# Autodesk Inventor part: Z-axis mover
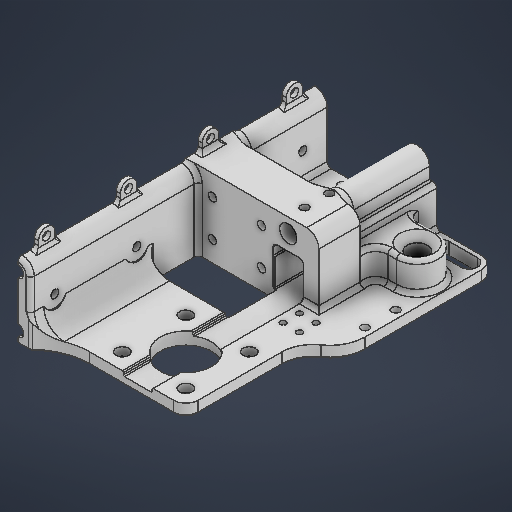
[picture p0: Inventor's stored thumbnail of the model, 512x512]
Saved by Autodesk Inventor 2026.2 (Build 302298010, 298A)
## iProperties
Created: 2026-04
Part Number: Z-axis mover
Material: 일반
Document SubType Name: Modeling
Designer: work
Density: 1 g/cm^3
Appearance: 기본값
Author: work
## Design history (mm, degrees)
sketch "스케치1"
  geometry: L1 (0, 0)-(8, 0); L2 (0, 0)-(0, 8); L3 (0, 0)-(-8, 0); L4 (0, 0)-(0, -8); L5 (0, 0)-(50, 0); L6 (0, 0)-(-50, 0); L7 (0, 0)-(0, 50); L8 (25, 0)-(25, -380); L9 (-25, 0)-(-25, -380); L10 (-25, 0)-(-25, 70); L11 (25, -380)-(-25, -380); L12 (25, 0)-(25, 0); L13 (25, 0)-(25, 120); L14 (-37.5, -395)-(37.5, -395); L15 (37.5, -395)-(37.5, -365); L16 (37.5, -365)-(-37.5, -365); L17 (-37.5, -365)-(-37.5, -395); L18 (-37.5, -395)-(37.5, -365); L19 (37.5, -395)-(-37.5, -365); L20 (-62.5, 38)-(62.5, 38); L21 (62.5, 38)-(62.5, -38); L22 (62.5, -38)-(-62.5, -38); L23 (-62.5, -38)-(-62.5, 38); L24 (-62.5, 38)-(62.5, -38); L25 (62.5, 38)-(-62.5, -38); L26 (62.5, -25)-(-62.5, -25); L27 (17, 38)-(-17, 38); L28 (-17, 38)-(-17, 61); L29 (-17, 61)-(17, 61); L30 (17, 61)-(17, 38); L31 (-22, 60.236)-(-22, 100); L32 (-22, 100)-(-28, 100); L33 (-28, 100)-(-28, -380); L34 (-28, -380)-(-22, -380); L35 (-22, -380)-(-22, 100); L36 (-40, 38)-(40, 38); L37 (40, 38)-(40, 18); L38 (40, 18)-(-40, 18); L39 (-40, 18)-(-40, 38); C1 r 5.25 at (0, 0); C2 r 11.3 at (0, 0); C3 r 2 at (8, 0); C4 r 2 at (0, 8); C5 r 2 at (-8, 0); C6 r 2 at (0, -8); C7 r 4.4 at (50, 0); C8 r 4.4 at (-50, 0); C9 r 4 at (0, 50); 7 further points
  constraints: 78 end point, 12 midpoint, 10 parallel, 9 centre point, 9 coincident, 8 horizontal, 6 perpendicular, 6 point on line, 5 vertical, 2 symmetric about line, 1 collinear, 22 other
  dimensions: "d0" = 10.5 diameter of C1; "d1" = 22.6 diameter of C2; "d2" = 8 distance of L1.start L1.end; "d3" = 4 diameter of C3; "d6" = 360 deg dimension on C1.centre L1.end (derived); "d8" = 50 distance of L4.start L5.end; "d9" = 8.8 diameter of C7; "d10" = 50 distance of L4.start L7.end; "d11" = 8 diameter of C9; "d12" = 12 distance of point (0, 38) L7.end; "d15" = 450 distance of L9.end L10.end; "d16" = 25 distance from line of point (0, 0) L8; "d17" = 25 distance from line of L10 C1.centre; "d19" = 500 distance of L8.end L13.end; "d20" = 120 vertical distance of point (0, 0) L13.end; "d21" = 75 distance between parallel lines of L17 L15; "d22" = 30 distance of L14.end L15.end; "d23" = 125 distance between parallel lines of L23 L21; "d24" = 25 distance from line of point (0, 0) L26; "d25" = 340 distance between parallel lines of L16 L26 (derived); "d26" = 34 distance of L28.end L29.end; "d27" = 23 distance of L27.end L28.end; "d30" = 6 distance between parallel lines of L33 L35; "d31" = 80 distance of L37.end L38.end; "d32" = 20 distance of L36.end L37.end; "d60" = 30 distance of L10.end point (-25, 100)
  node "스케치 - 원형 패턴1" dims "d6" = 360 deg (derived)
extrude "돌출1" new body sketch "스케치1" distance "d33" = 6; taper "d34" = 0 deg
extrude "돌출2" join sketch "스케치1" distance "d35" = 4; taper "d36" = 0 deg
extrude "돌출3" join sketch "스케치1" distance "d37" = 38; taper "d38" = 0 deg
sketch "스케치2"
  geometry: L1 (102.5, 6)-(22.5, 6) reference; L2 (87.5, 6)-(87.5, 31); L3 (93.5, 6)-(93.5, 31); L4 (81.5, 31)-(81.5, 6); L5 (0, 0)-(125, 0) reference; L6 (62.5, 6)-(37.5, 6); L7 (37.5, 6)-(37.5, 31); L8 (37.5, 31)-(62.5, 31); L9 (62.5, 31)-(62.5, 6); L10 (30.5, 4)-(44.5, 4); L11 (44.5, 4)-(44.5, 18); L12 (44.5, 18)-(30.5, 18); L13 (30.5, 18)-(30.5, 4); L14 (30.5, 4)-(44.5, 18); L15 (44.5, 4)-(30.5, 18); L16 (44.5, -10.5)-(86.5, -10.5); L17 (86.5, -10.5)-(86.5, 32.5); L18 (86.5, 32.5)-(44.5, 32.5); L19 (44.5, 32.5)-(44.5, -10.5); L20 (44.5, -10.5)-(86.5, 32.5); L21 (86.5, -10.5)-(44.5, 32.5); L22 (47.5, 32.5)-(47.5, -10.5); L23 (37.5, 6)-(37.5, 31); L24 (43.5, 6)-(43.5, 31); L25 (31.5, 31)-(31.5, 6); L26 (47, 1.5)-(28, 1.5); L27 (28, 1.5)-(28, 20.5); L28 (28, 20.5)-(47, 20.5); L29 (47, 20.5)-(47, 1.5); L30 (47, 1.5)-(28, 20.5); L31 (28, 1.5)-(47, 20.5); C1 r 2.75 at (87.5, 6); C2 r 2.75 at (87.5, 31); C3 r 4.25 at (37.5, 31); A1 r 6 centre (87.5, 6) between (81.5, 6) and (93.5, 6); A2 r 6 centre (87.5, 31) between (93.5, 31) and (81.5, 31); A3 r 6 centre (37.5, 6) between (31.5, 6) and (43.5, 6); A4 r 6 centre (37.5, 31) between (43.5, 31) and (31.5, 31); 16 further points
  constraints: 62 end point, 11 midpoint, 10 parallel, 10 tangent, 8 point on circle, 7 centre point, 7 perpendicular, 5 point on line, 4 horizontal, 2 coincident
  dimensions: "d39" = 5.5 diameter of C1; "d40" = 25 distance of L2.start L6.start; "d41" = 25 distance of L2.start L2.end; "d42" = 5.5 diameter of C2; "d43" = 25 distance of L7.end L8.end; "d44" = 25 distance of L6.end L7.end; "d45" = 8.5 diameter of C3; "d46" = 14 distance of L11.end L12.end; "d47" = 14 distance of L10.end L11.end; "d48" = 43 distance of L16.end L17.end; "d50" = 20 distance of L7.end point (37.5, 11); "d51" = 39 distance between parallel lines of L17 L22; "d52" = 3 distance between parallel lines of L22 L19; "d59" = 2.5 distance between parallel lines of L28 L12
extrude "돌출4" join sketch "스케치2" distance "d53" = 145; taper "d54" = 0 deg
extrude "돌출5" cut sketch "스케치2" extent not by distance; stored distance "d55" = 10; taper "d56" = 0 deg
sketch "스케치3"
  geometry: L1 (-31.5, 20.5)-(-31.5, 31) reference; L2 (-43.5, 31)-(-43.5, 20.5) reference; L3 (-30.5, 4)-(-44.5, 4) reference; L4 (-44.5, 18)-(-30.5, 18) reference; L5 (-28, 20.5)-(-31.5, 20.5) reference; L6 (-43.5, 20.5)-(-47, 20.5) reference; L7 (-47, 1.5)-(-41.469, 1.5) reference; L8 (-33.531, 1.5)-(-28, 1.5) reference; L9 (-28, 1.5)-(-28, 20.5) reference; L10 (-30.5, 18)-(-30.5, 4) reference; L11 (-44.5, 4)-(-44.5, 18) reference; L12 (-47, 20.5)-(-47, 1.5) reference; C1 r 6 at (-37.5, 31); A1 r 6 centre (-37.5, 6) between (-41.469, 1.5) and (-33.531, 1.5) reference; A2 r 6 centre (-37.5, 31) between (-31.5, 31) and (-43.5, 31) reference; 5 further points
  constraints: 1 centre point, 1 concentric
extrude "돌출6" cut sketch "스케치3" stored distance "d57" = 145; taper "d58" = 0 deg
sketch "스케치5"
  geometry: L1 (29.25, 38)-(20.75, 38) reference; L2 (18, 38)-(32, 38) reference; L3 (32, 38)-(18, 38) reference; L4 (-25, 38)-(62.5, 38) reference; L5 (40, 38)-(62.5, 38) reference; L6 (-40, 38)-(40, 38) reference; L7 (-62.5, 38)-(-40, 38) reference; L8 (-62.5, 38)-(-25, 38) reference; L9 (-25, 38)-(-31, 38) reference; L10 (-31, 38)-(-19, 38) reference; L11 (-19, 38)-(-25, 38) reference; L12 (25, 38)-(25, 88); L13 (9.5, 103.5)-(40.5, 103.5); L14 (40.5, 103.5)-(40.5, 72.5); L15 (40.5, 72.5)-(9.5, 72.5); L16 (9.5, 72.5)-(9.5, 103.5); L17 (9.5, 103.5)-(40.5, 72.5); L18 (40.5, 103.5)-(9.5, 72.5); L19 (1.5, 111.5)-(48.5, 111.5); L20 (48.5, 111.5)-(48.5, 64.5); L21 (48.5, 64.5)-(1.5, 64.5); L22 (1.5, 64.5)-(1.5, 111.5); L23 (1.5, 111.5)-(48.5, 64.5); L24 (48.5, 111.5)-(1.5, 64.5); L25 (-22.25, 120)-(-22.25, -25) reference; L26 (-31, 38)-(-19, 38) reference; L27 (-31, 38)-(-31, 120) reference; L28 (-19, 120)-(-31, 120) reference; L29 (-19, 38)-(-19, 120) reference; L30 (62.5, 38)-(62.5, -25) reference; L31 (40, 18)-(40, 38) reference; L32 (-62.5, 38)-(-25, 38) reference; L33 (-62.5, -25)-(-62.5, 38) reference; L34 (62.5, -25)-(-62.5, -25) reference; L35 (62.5, 38)-(62.5, -25) reference; L36 (-25, 38)-(62.5, 38) reference; L37 (-19, 38)-(19, 38); L38 (19, 38)-(19, 62); L39 (19, 62)-(-19, 62); L40 (-19, 62)-(-19, 38); L41 (-19, 38)-(-19, 120) reference; C1 r 12.5 at (25, 88); C2 r 2 at (9.5, 72.5); C3 r 2 at (40.5, 103.5); C4 r 2 at (9.5, 103.5); C5 r 2 at (40.5, 72.5); C6 r 2 at (0, -8) reference; C7 r 2 at (8, 0) reference; C8 r 2 at (0, 8) reference; C9 r 2 at (-8, 0) reference; C10 r 5.25 at (0, 0) reference; C11 r 4.4 at (50, 0) reference; C12 r 4.4 at (-50, 0) reference; A1 r 28.971 centre (1.5, 140.471) between (-19, 120) and (1.5, 111.5); A2 r 15 centre (63.5, 64.5) between (48.5, 64.5) and (55.046, 52.109); A3 r 17.08 centre (45.42, 38) between (62.5, 38) and (55.046, 52.109); 15 further points
  constraints: 34 end point, 8 centre point, 6 parallel, 6 point on circle, 5 coincident, 5 midpoint, 4 perpendicular, 4 tangent, 3 horizontal, 2 point on line, 5 other
  dimensions: "d61" = 25 distance from line of point (0, 38) L12; "d62" = 25 diameter of C1; "d63" = 31 distance of L14.end L15.end; "d64" = 31 distance of L13.end L14.end; "d65" = 4 diameter of C2; "d66" = 4 diameter of C3; "d67" = 4 diameter of C4; "d68" = 4 diameter of C5; "d69" = 50 distance of L12.start L12.end; "d70" = 8 distance between parallel lines of L14 L20; "d71" = 15 radius of A2; "d73" = 24 distance of L39.end L37.start
extrude "돌출7" join sketch "스케치5" distance "d74" = 6; taper "d75" = 0 deg
sketch "스케치6"
  geometry: L1 (-81.5, 31)-(-81.5, 0) reference; L2 (-81.5, 0)-(-43.5, 0) reference; L3 (-43.5, 0)-(-43.5, 4) reference; L4 (-30.5, 6)-(-22.5, 6) reference; L5 (-44.5, 18)-(-44.5, 4) reference; L6 (-30.5, 18)-(-44.5, 18) reference; L7 (-30.5, 6)-(-30.5, 18) reference; L8 (-22.5, 6)-(-22.5, 38) reference; L9 (-102.5, 38)-(-22.5, 38) reference; L10 (-102.5, 6)-(-102.5, 38) reference; L11 (-125, 6)-(-102.5, 6) reference; L12 (-125, 0)-(-125, 6) reference; L13 (-125, 0)-(-93.5, 0) reference; L14 (-93.5, 0)-(-93.5, 31) reference; L15 (-81.5, 6)-(-81.5, 31) reference; L16 (-93.5, 31)-(-93.5, 0) reference; L17 (0, 0)-(-125, 0) reference; L18 (-93.5, 6)-(-81.5, 6); L19 (-81.5, 6)-(-81.5, 0); L20 (-81.5, 0)-(-93.5, 0); L21 (-93.5, 0)-(-93.5, 6); L22 (-81.5, 0)-(-93.5, 0) reference; L23 (-81.5, 0)-(-81.5, 6) reference; L24 (-90.25, 6)-(-84.75, 6) reference; L25 (-44.5, 4)-(-43.5, 4) reference; C1 r 4.25 at (-37.5, 31) reference; C2 r 2.75 at (-87.5, 31) reference; A1 r 6 centre (-87.5, 31) between (-81.5, 31) and (-93.5, 31) reference; A2 r 6 centre (-87.5, 31) between (-81.5, 31) and (-93.5, 31) reference; A3 r 2.75 centre (-87.5, 6) between (-84.75, 6) and (-90.25, 6) reference; 10 further points
  constraints: 8 end point, 2 parallel, 2 point on line, 1 horizontal, 1 perpendicular
extrude "돌출8" join sketch "스케치6" stored distance "d76" = 6; taper "d77" = 0 deg
sketch "스케치7"
  geometry: L1 (47, 6)-(81.5, 6) reference; L2 (47, 20.5)-(43.5, 20.5) reference; L3 (43.5, 20.5)-(43.5, 31) reference; L4 (31.5, 31)-(31.5, 20.5) reference; L5 (31.5, 20.5)-(28, 20.5) reference; L6 (28, 20.5)-(28, 6) reference; L7 (0, 6)-(28, 6) reference; L8 (0, 0)-(0, 6) reference; L9 (0, 0)-(125, 0) reference; L10 (125, 0)-(125, 6) reference; L11 (93.5, 6)-(125, 6) reference; L12 (93.5, 6)-(93.5, 31) reference; L13 (81.5, 31)-(81.5, 6) reference; L14 (44.5, 18)-(44.5, 4) reference; L15 (44.5, 4)-(30.5, 4) reference; L16 (30.5, 4)-(30.5, 18) reference; L17 (30.5, 18)-(44.5, 18) reference; L18 (43.5, 4)-(30.5, 4) reference; L19 (43.5, 4)-(43.5, 6) reference; L20 (30.5, 6)-(43.5, 6) reference; L21 (30.5, 4)-(30.5, 6) reference; L22 (81.5, 0)-(43.5, 0) reference; L23 (81.5, 0)-(81.5, 6) reference; L24 (43.5, 6)-(81.5, 6) reference; L25 (43.5, 0)-(43.5, 6) reference; L26 (47, 6)-(47, 20.5) reference; C1 r 2.75 at (87.5, 31) reference; C2 r 2.75 at (87.5, 6) reference; C3 r 2.75 at (87.5, 31) reference; A1 r 6 centre (37.5, 31) between (43.5, 31) and (31.5, 31) reference; A2 r 6 centre (87.5, 31) between (93.5, 31) and (81.5, 31) reference; 4 further points
extrude "돌출9" cut sketch "스케치7" extent not by distance; stored distance "d78" = 0; taper "d79" = 0 deg
sketch "스케치8"
  geometry: L1 (50.5, 10)-(74.5, 10); L2 (74.5, 10)-(74.5, 28); L3 (74.5, 28)-(50.5, 28); L4 (50.5, 28)-(50.5, 10); L5 (50.5, 10)-(74.5, 28); L6 (74.5, 10)-(50.5, 28); L7 (102.5, 38)-(22.5, 38) reference; L8 (62.5, 38)-(62.5, 0); C1 r 2 at (50.5, 28); C2 r 2 at (50.5, 10); C3 r 2 at (74.5, 10); C4 r 2 at (74.5, 28); 1 further point
  constraints: 14 end point, 4 centre point, 4 coincident, 4 midpoint, 2 parallel, 1 horizontal, 1 perpendicular, 1 vertical
  dimensions: "d80" = 24 distance of L3.end L2.end; "d81" = 18 distance of L2.end L1.end; "d82" = 4 diameter of C1; "d83" = 4 diameter of C2; "d84" = 4 diameter of C3; "d85" = 4 diameter of C4
extrude "돌출10" cut sketch "스케치8" extent not by distance; stored distance "d86" = 18 (derived); taper "d87" = 0 deg
sketch "스케치9"
  geometry: L1 (59, -32)-(59, -7) reference; L2 (71, -7)-(71, -32) reference; L3 (80, -32)-(71, -32) reference; L4 (80, -32)-(80, 0) reference; L5 (0, 0)-(80, 0) reference; L6 (0, -32)-(0, 0) reference; L7 (5.5, -32)-(0, -32) reference; L8 (5.5, -32)-(5.5, -17.5) reference; L9 (5.5, -17.5)-(9, -17.5) reference; L10 (9, -17.5)-(9, -7) reference; L11 (21, -7)-(21, -17.5) reference; L12 (21, -17.5)-(24.5, -17.5) reference; L13 (59, -32)-(24.5, -32) reference; L14 (24.5, -17.5)-(24.5, -32) reference; C1 r 2 at (28, -28) reference; C2 r 2 at (52, -28) reference; C3 r 2 at (28, -10) reference; C4 r 2 at (52, -10) reference; C5 r 2 at (52, -28) reference; A1 r 6 centre (65, -7) between (71, -7) and (59, -7) reference; A2 r 6 centre (15, -7) between (21, -7) and (9, -7) reference; 5 further points
  constraints: 4 coincident
hole "구멍1" sketch "스케치9" at (52, -10), (28, -10), (28, -28), (52, -28) diameter "d88" = 4; stored, may be unused: countersink angle "d92" = 90 deg, drill point angle "d94" = 0 deg; dims "d89" = 6, "d90" = 6.2, "d91" = 4, "d93" = 8
sketch "스케치10"
  geometry: L1 (32, -98.356)-(32, -111.5) reference; L2 (32, -111.5)-(48.5, -111.5) reference; L3 (48.5, -111.5)-(48.5, -64.5) reference; L4 (62.5, -38)-(62.5, 25) reference; L5 (62.5, 25)-(34.5, 25) reference; L6 (34.5, 25)-(34.5, -18) reference; L7 (34.5, -18)-(40, -18) reference; L8 (40, -18)-(40, -38) reference; L9 (32, -38)-(40, -38) reference; L10 (32, -38)-(32, -77.644) reference; L11 (-31, -18)-(-31, 25) reference; L12 (-31, 25)-(-62.5, 25) reference; L13 (-62.5, 25)-(-62.5, -38) reference; L14 (-62.5, -38)-(-40, -38) reference; L15 (-40, -38)-(-40, -18) reference; L16 (-40, -18)-(-31, -18) reference; L17 (-50, -10)-(-31, -10); L18 (-50, 10)-(-31, 10); L19 (50, 10)-(34.5, 10); L20 (50, -10)-(34.5, -10); C1 r 4.4 at (50, 0) reference; C2 r 2 at (40.5, -72.5) reference; C3 r 2 at (40.5, -103.5) reference; C4 r 4.4 at (-50, 0) reference; A1 r 15 centre (63.5, -64.5) between (55.046, -52.109) and (48.5, -64.5) reference; A2 r 17.08 centre (45.42, -38) between (55.046, -52.109) and (62.5, -38) reference; A3 r 12.5 centre (25, -88) between (32, -98.356) and (32, -77.644) reference; A4 r 10 centre (-50, 0) between (-50, -10) and (-50, 10); A5 r 10 centre (50, 0) between (50, 10) and (50, -10); 1 further point
  constraints: 8 end point, 4 perpendicular, 4 point on circle, 4 point on line, 4 tangent, 2 centre point, 2 coincident
  dimensions: "d95" = 20 diameter of A4; "d96" = 20 diameter of A5
extrude "돌출11" join sketch "스케치10" stored distance "d97" = 10; taper "d98" = 0 deg
fillet "모깎기1" dims "d99" = 6
sketch "스케치11"
  geometry: C1 r 4.25 at (0, 0) reference; 1 further point
extrude "돌출12" cut sketch "스케치11" extent not by distance; stored distance "d100" = 0; taper "d101" = 0 deg
fillet "모깎기2" dims "d102" = 2
fillet "모깎기3" dims "d103" = 0.5
chamfer "모따기1" distance "d104" = 1; stored, may be unused: second distance "d105" = 2, angle "d106" = 45 deg
sketch "스케치12" dims "d0" = 10.5, "d1" = 22.6, "d2" = 8, "d3" = 4, "d6" = 360 deg (derived), "d8" = 50, "d9" = 8.8, "d10" = 50, "d11" = 8, "d12" = 12, "d15" = 450, "d16" = 25, "d17" = 25, "d19" = 500, "d20" = 120, "d21" = 75, "d22" = 30, "d23" = 125, "d24" = 25, "d25" = 340 (derived), "d26" = 34, "d27" = 23, "d30" = 6, "d31" = 80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
  geometry: L1 (17.5, -61.936)-(17.5, -78) reference; L2 (17, -62)-(-17, -62) reference; L3 (-19, -60)-(-19, -118) reference; L4 (-21, -120)-(-19.813, -120) reference; L5 (1.5, -111.5)-(17.5, -111.5) reference; L6 (17.5, -98)-(17.5, -111.5) reference; L7 (42, -40)-(42, -17.621) reference; L8 (32.5, -78)-(32.5, -40) reference; L9 (32.5, -111.5)-(32.5, -98) reference; L10 (32.5, -111.5)-(42.5, -111.5) reference; L11 (48.5, -105.5)-(48.5, -64.5) reference; L12 (62.5, -38)-(62.5, 19) reference; L13 (56.5, 25)-(36.5, 25) reference; L14 (36.5, 16)-(36.5, 25) reference; L15 (50, 12)-(40.5, 12) reference; L16 (45.657, -12)-(50, -12) reference; L17 (42, -40)-(42, -17.621) reference; L18 (32.5, -40)-(42, -40) reference; C1 r 2 at (9.5, -72.5) reference; C2 r 2 at (9.5, -103.5) reference; C3 r 2 at (40.5, -103.5) reference; C4 r 2 at (40.5, -72.5) reference; C5 r 2 at (40.5, -103.5) reference; A1 r 2 centre (17, -60) between (17, -62) and (17.5, -61.936) reference; A2 r 2 centre (-17, -60) between (-19, -60) and (-17, -62) reference; A3 r 2 centre (-21, -118) between (-21, -120) and (-19, -118) reference; A4 r 2 centre (-19.813, -118) between (-19.813, -120) and (-18.437, -119.451) reference; A5 r 28.971 centre (1.5, -140.471) between (1.5, -111.5) and (-18.437, -119.451) reference; A6 r 12.5 centre (25, -88) between (17.5, -78) and (17.5, -98) reference; A7 r 12.5 centre (25, -88) between (32.5, -98) and (32.5, -78) reference; A8 r 6 centre (42.5, -105.5) between (42.5, -111.5) and (48.5, -105.5) reference; A9 r 15 centre (63.5, -64.5) between (55.046, -52.109) and (48.5, -64.5) reference; A10 r 17.08 centre (45.42, -38) between (55.046, -52.109) and (62.5, -38) reference; A11 r 6 centre (56.5, 19) between (62.5, 19) and (56.5, 25) reference; A12 r 4 centre (40.5, 16) between (36.5, 16) and (40.5, 12) reference; A13 r 12 centre (50, 0) between (50, -12) and (50, 12) reference; A14 r 4 centre (45.657, -16) between (45.657, -12) and (42, -17.621) reference; 5 further points
  constraints: 4 coincident
hole "구멍2" sketch "스케치12" at (9.5, -103.5), (40.5, -103.5), (40.5, -72.5), (9.5, -72.5) diameter "d107" = 4; stored, may be unused: countersink angle "d111" = 90 deg, drill point angle "d113" = 0 deg; dims "d6" = 360 deg (derived), "d25" = 340 (derived), "d108" = 6, "d109" = 6.2, "d110" = 4, "d112" = 8
fillet "모깎기4" dims "d114" = 10
sketch "스케치13"
  geometry: L1 (78, -30)-(0, -30) reference; L2 (78, 0)-(78, -30) reference; L3 (0, 0)-(78, 0) reference; L4 (0, -30)-(0, 0) reference; L5 (68, 0)-(28, 0); L6 (28, 0)-(28, -25); L7 (28, -25)-(68, -25); L8 (68, -25)-(68, 0); C1 r 4 at (28, 0); C2 r 4 at (28, -25); C3 r 4 at (68, -25); C4 r 4 at (68, 0); 1 further point
  constraints: 8 end point, 4 centre point, 2 parallel, 1 coincident, 1 horizontal, 1 perpendicular, 1 point on line
  dimensions: "d115" = 40 distance of L7.end L6.end; "d116" = 25 distance of L6.end L5.end; "d117" = 10 distance between parallel lines of L2 L8; "d118" = 8 diameter of C1; "d119" = 8 diameter of C2; "d120" = 8 diameter of C3; "d121" = 8 diameter of C4
  node "투영된 루프17"
extrude "돌출13" join sketch "스케치13" stored distance "d122" = 8 (derived); taper "d123" = 0 deg
extrude "돌출14" join sketch "스케치13" distance "d124" = 1.5; taper "d125" = 0 deg
sketch "스케치14"
  geometry: L1 (4, 0)-(36, 0) reference; L2 (-28, 0)-(-4, 0) reference; L3 (-28, -30)-(-28, 0) reference; L4 (50, -30)-(-28, -30) reference; L5 (50, 0)-(50, -30) reference; L6 (44, 0)-(50, 0) reference; C1 r 4 at (40, -25) reference; C2 r 4 at (0, -25) reference; C3 r 2 at (0, 0); C4 r 2 at (0, -25); C5 r 2 at (40, -25); C6 r 2 at (40, 0); A1 r 4 centre (40, 0) between (36, 0) and (44, 0) reference; A2 r 4 centre (0, 0) between (-4, 0) and (4, 0) reference; 1 further point
  constraints: 4 centre point, 4 coincident
  dimensions: "d126" = 4 diameter of C3; "d127" = 4 diameter of C4; "d128" = 4 diameter of C5; "d129" = 4 diameter of C6
  node "투영된 루프18"
extrude "돌출15" cut sketch "스케치14" stored distance "d130" = 1.5; taper "d131" = 0 deg
extrude "돌출16" cut sketch "스케치14" stored distance "d132" = 10; taper "d133" = 0 deg
fillet "모깎기5" dims "d134" = 2
sketch "스케치15"
  geometry: L1 (-21.127, -38)-(34, -38) reference; L2 (25, -38)-(25, -18); C1 r 2 at (25, -18); C2 r 2 at (25, -30); 1 further point
  constraints: 2 centre point, 2 end point, 2 point on line, 1 coincident, 1 vertical
  dimensions: "d135" = 20 distance of L2.start L2.end; "d136" = 25 distance from line of L2 point (0, 0); "d137" = 4 diameter of C1; "d138" = 4 diameter of C2; "d139" = 12 distance of L2.end C2.centre
extrude "돌출17" cut sketch "스케치15" stored distance "d140" = 10; taper "d141" = 0 deg; dims "d9" = 8.8
sketch "스케치16" dims "d145" = 7
  geometry: L1 (13, -21.5)-(13, -1.9); L2 (8, -25)-(31.5, -25) reference; L3 (6, -23)-(6, 0) reference; L4 (13, -5.4)-(6, -5.4); L5 (13, 1.6)-(5.783, 1.6); L6 (13, -18)-(6, -18); L7 (-42.5, -26.5)-(-42.5, -13.5) reference; L8 (-56.5, -27.5)-(-43.5, -27.5) reference; L9 (-57.5, -13.5)-(-57.5, -26.5) reference; L10 (-43.5, -12.5)-(-56.5, -12.5) reference; L11 (31.5, -30)-(-81.5, -30) reference; L12 (31.5, -25)-(31.5, -30) reference; L13 (8, -25)-(31.5, -25) reference; L14 (6, -23)-(6, 0) reference; L15 (-6, 0)-(-6, -23) reference; L16 (-38.5, -25)-(-8, -25) reference; L17 (-40.5, -23)-(-40.5, -12.5) reference; L18 (-42.5, -10.5)-(-44, -10.5) reference; L19 (-44, -10.5)-(-44, 0) reference; L20 (-56, 0)-(-56, -10.5) reference; L21 (-56, -10.5)-(-57.5, -10.5) reference; L22 (-59.5, -12.5)-(-59.5, -23) reference; L23 (-81.5, -25)-(-61.5, -25) reference; L24 (-81.5, -30)-(-81.5, -25) reference; C1 r 2 at (13, -21.5); C2 r 2 at (13, -1.9); C3 r 4.25 at (-50, 0) reference; C4 r 2.75 at (0, 0) reference; C5 r 2.75 at (0, -25) reference; A1 r 3.5 centre (13, -1.9) between (13, -5.4) and (13, 1.6); A2 r 6 centre (0, 0) between (6, 0) and (-6, 0) reference; A3 r 1 centre (-43.5, -13.5) between (-42.5, -13.5) and (-43.5, -12.5) reference; A4 r 1 centre (-43.5, -26.5) between (-43.5, -27.5) and (-42.5, -26.5) reference; A5 r 1 centre (-56.5, -26.5) between (-57.5, -26.5) and (-56.5, -27.5) reference; A6 r 1 centre (-56.5, -13.5) between (-56.5, -12.5) and (-57.5, -13.5) reference; A7 r 2 centre (8, -23) between (6, -23) and (8, -25) reference; A8 r 6 centre (0, 0) between (6, 0) and (-6, 0) reference; A9 r 2 centre (-8, -23) between (-8, -25) and (-6, -23) reference; A10 r 2 centre (-38.5, -23) between (-40.5, -23) and (-38.5, -25) reference; A11 r 2 centre (-42.5, -12.5) between (-40.5, -12.5) and (-42.5, -10.5) reference; A12 r 6 centre (-50, 0) between (-44, 0) and (-56, 0) reference; A13 r 2 centre (-57.5, -12.5) between (-57.5, -10.5) and (-59.5, -12.5) reference; A14 r 2 centre (-61.5, -23) between (-61.5, -25) and (-59.5, -23) reference; 5 further points
  constraints: 8 end point, 4 point on line, 3 centre point, 3 coincident, 3 perpendicular, 3 point on circle, 2 horizontal, 1 tangent, 1 vertical, 3 other
  dimensions: "d142" = 4 diameter of C1; "d143" = 4 diameter of C2; "d144" = 7 diameter of A1; "d146" = 19.6 distance of L1.start L1.end; "d147" = 7 distance from line of L3 L1.start
extrude "돌출18" join sketch "스케치16" distance "d148" = 3; taper "d149" = 0 deg
fillet "모깎기6" dims "d150" = 1
sketch "스케치17"
  geometry: L1 (0, 0)-(0, 25); L2 (13.5, 25)-(-17, 25) reference; L3 (7.5, 21)-(-7.5, 21); L4 (58.5, -34)-(58.5, -19); L5 (62.5, -38)-(62.5, 19) reference; C1 r 2 at (-7.5, 21); C2 r 2 at (7.5, 21); C3 r 2 at (58.5, -34); C4 r 2 at (58.5, -19); 1 further point
  constraints: 6 end point, 4 centre point, 4 coincident, 2 point on line, 2 vertical, 1 horizontal, 1 midpoint
  dimensions: "d151" = 15 distance of L3.start L3.end; "d152" = 4 diameter of C1; "d153" = 4 diameter of C2; "d154" = 4 distance between parallel lines of L2 L3; "d155" = 15 distance of L4.start L4.end; "d156" = 4 diameter of C3; "d157" = 4 diameter of C4; "d158" = 4 distance between parallel lines of L5 L4; "d159" = 4 horizontal distance of L5.start L4.start
extrude "돌출19" cut sketch "스케치17" extent not by distance; stored distance "d160" = 0; taper "d161" = 0 deg
sketch "스케치18"
  geometry: L1 (-42, -17.621)-(-42, -38) reference; L2 (-50, -12)-(-45.657, -12) reference; C1 r 16 at (-60, -30); 1 further point
  constraints: 1 centre point
  dimensions: "d162" = 32 diameter of C1; "d163" = 2 distance edge to line of C1 L1; "d164" = 2 distance edge to line of C1 L2
extrude "돌출20" cut sketch "스케치18" distance "d165" = 2; taper "d166" = 0 deg
sketch "스케치19"
  geometry: L1 (56.5, 19)-(42.5, 19); L2 (56.5, 23)-(42.5, 23); L3 (42.5, 15)-(56.5, 15); L4 (36.5, 16)-(36.5, 25) reference; L5 (-56.5, 19)-(-48, 19); L6 (-56.5, 15)-(-48, 15); L7 (-48, 23)-(-56.5, 23); L8 (-46.144, -38)-(-42, -38) reference; L9 (-42, -17.621)-(-42, -38) reference; L10 (-50, -12)-(-45.657, -12) reference; L11 (-37, 12)-(-50, 12) reference; L12 (-33, 21)-(-33, 16) reference; L13 (-41.742, 21)-(-33, 21) reference; L14 (-41.742, 25)-(-56.5, 25) reference; L15 (-62.5, 19)-(-62.5, -14.197) reference; L16 (36.5, -52)-(44.5, -52); L17 (44.5, -52)-(44.5, -44); L18 (44.5, -44)-(36.5, -44); L19 (36.5, -44)-(36.5, -52); L20 (32.5, -40)-(42, -40) reference; L21 (32.5, -78)-(32.5, -40) reference; L22 (13.5, 25)-(13.5, -16.011) reference; L23 (13.5, 25)-(-17, 25) reference; L24 (-17, -12)-(-17, 25) reference; L25 (9.631, -16)-(-9.631, -16) reference; L26 (32.5, -78)-(32.5, -40) reference; L27 (32.5, -111.5)-(32.5, -98) reference; L28 (32.5, -111.5)-(42.5, -111.5) reference; L29 (48.5, -105.5)-(48.5, -64.5) reference; L30 (62.5, -38)-(62.5, 19) reference; L31 (56.5, 25)-(36.5, 25) reference; L32 (36.5, 16)-(36.5, 25) reference; L33 (50, 12)-(40.5, 12) reference; L34 (45.657, -12)-(50, -12) reference; L35 (42, -40)-(42, -17.621) reference; L36 (32.5, -40)-(42, -40) reference; L37 (-41.742, 25)-(-41.742, 21) reference; C1 r 1.5 at (36.5, -52); C2 r 1.5 at (36.5, -44); C3 r 1.5 at (44.5, -44); C4 r 1.5 at (44.5, -52); A1 r 4 centre (56.5, 19) between (56.5, 15) and (56.5, 23); A2 r 4 centre (42.5, 19) between (42.5, 23) and (42.5, 15); A3 r 6 centre (56.5, 19) between (62.5, 19) and (56.5, 25) reference; A4 r 4 centre (-56.5, 19) between (-56.5, 23) and (-56.5, 15); A5 r 4 centre (-48, 19) between (-48, 15) and (-48, 23); A6 r 6 centre (-56.5, 19) between (-56.5, 25) and (-62.5, 19) reference; A7 r 16 centre (-60, -30) between (-46.144, -38) and (-62.5, -14.197) reference; A8 r 4 centre (-45.657, -16) between (-42, -17.621) and (-45.657, -12) reference; A9 r 12 centre (-50, 0) between (-50, 12) and (-50, -12) reference; A10 r 4 centre (-37, 16) between (-37, 12) and (-33, 16) reference; A11 r 6 centre (-56.5, 19) between (-56.5, 25) and (-62.5, 19) reference; A12 r 4 centre (-13, -12) between (-17, -12) and (-13.912, -15.895) reference; A13 r 12.5 centre (25, -88) between (32.5, -98) and (32.5, -78) reference; A14 r 6 centre (42.5, -105.5) between (42.5, -111.5) and (48.5, -105.5) reference; A15 r 15 centre (63.5, -64.5) between (55.046, -52.109) and (48.5, -64.5) reference; A16 r 17.08 centre (45.42, -38) between (55.046, -52.109) and (62.5, -38) reference; A17 r 6 centre (56.5, 19) between (62.5, 19) and (56.5, 25) reference; A18 r 4 centre (40.5, 16) between (36.5, 16) and (40.5, 12) reference; A19 r 12 centre (50, 0) between (50, -12) and (50, 12) reference; A20 r 4 centre (45.657, -16) between (45.657, -12) and (42, -17.621) reference; 8 further points
  constraints: 24 end point, 10 point on circle, 8 centre point, 8 tangent, 4 coincident, 4 parallel, 3 horizontal, 3 midpoint, 2 concentric, 1 perpendicular, 4 other
  dimensions: "d167" = 8 diameter of A2; "d168" = 2 distance from line of point (38.5, 19) L4; "d169" = 8 diameter of A5; "d171" = 3 diameter of C1; "d172" = 3 diameter of C2; "d173" = 3 diameter of C3; "d174" = 3 diameter of C4; "d175" = 8 distance of L16.end L17.end; "d176" = 8 distance of L17.end L18.end; "d177" = 4 distance between parallel lines of L20 L18; "d178" = 4 distance from line of L21 point (36.5, -48)
extrude "돌출21" cut sketch "스케치19" extent not by distance; stored distance "d179" = 0; taper "d180" = 0 deg
sketch "스케치20"
  geometry: 1 further point
sketch "스케치21"
  geometry: L1 (7.5, -26.5)-(7.5, -13.5) reference; L2 (-6.5, -27.5)-(6.5, -27.5) reference; L3 (-7.5, -13.5)-(-7.5, -26.5) reference; L4 (6.5, -12.5)-(-6.5, -12.5) reference; L5 (81.5, -30)-(-31.5, -30) reference; L6 (81.5, -25)-(81.5, -30) reference; L7 (66.742, -25)-(81.5, -25) reference; L8 (63, -18)-(57, -18) reference; L9 (56, -17)-(56, -6.4) reference; L10 (57, -5.4)-(63, -5.4) reference; L11 (63, 1.6)-(56.499, 1.6) reference; L12 (44, 0)-(44, -23) reference; L13 (11.5, -25)-(42, -25) reference; L14 (9.5, -23)-(9.5, -12.5) reference; L15 (7.5, -10.5)-(6, -10.5) reference; L16 (6, -10.5)-(6, 0) reference; L17 (-6, 0)-(-6, -10.5) reference; L18 (-6, -10.5)-(-7.5, -10.5) reference; L19 (-9.5, -12.5)-(-9.5, -23) reference; L20 (-31.5, -25)-(-11.5, -25) reference; L21 (-31.5, -30)-(-31.5, -25) reference; L22 (-9.5, -12.5)-(-9.5, -7.5); L23 (-7.5, -5.5)-(7.5, -5.5); L24 (9.5, -12.5)-(9.5, -7.5); L25 (7.5, -13.5)-(7.5, -7.5); L26 (7.5, -7.5)-(-7.5, -7.5); L27 (-7.5, -7.5)-(-7.5, -13.5); L28 (-9.5, -13.5)-(9.5, -13.5); C1 r 2 at (63, -1.9) reference; C2 r 2 at (63, -21.5) reference; C3 r 4.25 at (0, 0) reference; C4 r 2.75 at (50, 0) reference; C5 r 2.75 at (50, -25) reference; A1 r 1 centre (6.5, -13.5) between (7.5, -13.5) and (6.5, -12.5) reference; A2 r 1 centre (6.5, -26.5) between (6.5, -27.5) and (7.5, -26.5) reference; A3 r 1 centre (-6.5, -26.5) between (-7.5, -26.5) and (-6.5, -27.5) reference; A4 r 1 centre (-6.5, -13.5) between (-6.5, -12.5) and (-7.5, -13.5) reference; A5 r 1 centre (66.742, -24) between (65.91, -23.444) and (66.742, -25) reference; A6 r 3.5 centre (63, -21.5) between (65.91, -23.444) and (63, -18) reference; A7 r 1 centre (57, -17) between (56, -17) and (57, -18) reference; A8 r 1 centre (57, -6.4) between (57, -5.4) and (56, -6.4) reference; A9 r 3.5 centre (63, -1.9) between (63, -5.4) and (63, 1.6) reference; A10 r 1 centre (56.499, 2.6) between (55.571, 2.229) and (56.499, 1.6) reference; A11 r 6 centre (50, 0) between (55.571, 2.229) and (44, 0) reference; A12 r 2 centre (42, -23) between (42, -25) and (44, -23) reference; A13 r 2 centre (11.5, -23) between (9.5, -23) and (11.5, -25) reference; A14 r 2 centre (7.5, -12.5) between (9.5, -12.5) and (7.5, -10.5) reference; A15 r 6 centre (0, 0) between (6, 0) and (-6, 0) reference; A16 r 2 centre (-7.5, -12.5) between (-7.5, -10.5) and (-9.5, -12.5) reference; A17 r 2 centre (-11.5, -23) between (-11.5, -25) and (-9.5, -23) reference; A18 r 2 centre (-7.5, -7.5) between (-7.5, -5.5) and (-9.5, -7.5); A19 r 2 centre (7.5, -7.5) between (9.5, -7.5) and (7.5, -5.5); A20 r 2 centre (-5.5, -9.5) between (-5.5, -7.5) and (-7.5, -9.5); A21 r 2 centre (5.5, -9.5) between (7.5, -9.5) and (5.5, -7.5); 8 further points
  constraints: 14 end point, 8 point on circle, 8 tangent, 6 point on line, 4 centre point, 2 vertical, 1 horizontal, 1 midpoint, 1 perpendicular, 12 other
  dimensions: "d181" = 7 distance from line of L4 point (0, -5.5); "d182" = 2 radius of A19; "d183" = 2 radius of A18; "d184" = 2 radius of A20; "d185" = 2 radius of A21; "d186" = 1 distance between parallel lines of L4 L28
  node "투영된 루프21"
extrude "돌출22" join sketch "스케치21" stored distance "d187" = 10; taper "d188" = 0 deg
extrude "돌출23" cut sketch "스케치21" extent not by distance; stored distance "d189" = 10; taper "d190" = 0 deg
chamfer "모따기2" distance "d191" = 0.5; stored, may be unused: second distance "d192" = 2, angle "d193" = 45 deg
node "작업 평면1"
sketch "스케치22"
  geometry: L1 (-37, 16.5)-(0, 16.5) reference; L2 (5.97, 17.5)-(26, 17.5) reference; L3 (28, 16.5)-(106, 16.5) reference; L4 (96, 12.5)-(96, 20.5); L5 (100, 12.5)-(100, 20.5); L6 (92, 20.5)-(92, 12.5); L7 (108, 13.25)-(108, 7.75) reference; L8 (52, 20.5)-(52, 12.5); L9 (60, 12.5)-(60, 20.5); L10 (56, 12.5)-(56, 20.5); L11 (11.985, 21.8)-(11.985, 14.348); L12 (19.985, 11.991)-(19.985, 21.8); L13 (15.985, 13.2)-(15.985, 21.8); L14 (-29, 20.5)-(-29, 12.5); L15 (-21, 12.5)-(-21, 20.5); L16 (-25, 12.5)-(-25, 20.5); L17 (-29, 14.5)-(-21, 14.5); L18 (11.985, 15.5)-(19.985, 15.5); L19 (52, 14.5)-(60, 14.5); L20 (92, 14.5)-(100, 14.5); C1 r 2 at (96, 20.5); C2 r 2 at (56, 20.5); C3 r 2 at (15.985, 21.8); C4 r 2 at (-25, 20.5); A1 r 4 centre (96, 12.5) between (92, 12.5) and (100, 12.5); A2 r 4 centre (96, 20.5) between (100, 20.5) and (92, 20.5); A3 r 4 centre (56, 20.5) between (60, 20.5) and (52, 20.5); A4 r 4 centre (15.985, 21.8) between (19.985, 21.8) and (11.985, 21.8); A5 r 4 centre (-25, 20.5) between (-21, 20.5) and (-29, 20.5); 7 further points
  constraints: 40 end point, 15 point on line, 10 point on circle, 10 tangent, 9 centre point, 7 perpendicular, 5 midpoint, 4 coincident, 4 parallel, 2 other
  dimensions: "d194" = 4 distance of point (96, 16.5) L4.end; "d195" = 8 diameter of A2; "d196" = 4 diameter of C1; "d197" = 12 distance between parallel lines of L7 L4; "d198" = 8 diameter of A3; "d199" = 4 diameter of C2; "d200" = 8 diameter of A4; "d201" = 4 diameter of C3; "d202" = 8 diameter of A5; "d203" = 4 diameter of C4; "d204" = 40 distance between parallel lines of L4 L10; "d205" = 12 distance of L1.start point (-25, 16.5); "d206" = 2 distance between parallel lines of L20 L3; "d207" = 2 distance between parallel lines of L18 L2
extrude "돌출24" join sketch "스케치22" stored distance "d208" = 4; taper "d209" = 0 deg
sketch "스케치23"
  geometry: L1 (68, 30)-(68, 5); L2 (0, 30)-(78, 30) reference; L3 (28, 30)-(28, 5); L4 (80, 7.75)-(-65, 7.75) reference; L5 (68, 17.5)-(-65, 17.5); L6 (-65, 30)-(-65, 7) reference; L7 (-53, 40)-(-53, -1); L8 (-8.015, 37)-(-16.015, 37) reference; L9 (-8.015, 37)-(-8.015, 41.3) reference; L10 (-16.015, 41.3)-(-16.015, 37) reference; L11 (-12.015, 41.3)-(-12.015, -1); L12 (-2, -1)-(-59, -1) reference; C1 r 2 at (28, 30) reference; C2 r 2 at (68, 30) reference; C3 r 2 at (68, 5) reference; C4 r 2 at (28, 5) reference; C5 r 2 at (-53, 40) reference; C6 r 2 at (-53, 17.5); C7 r 2 at (28, 17.5); C8 r 2 at (68, 17.5); C9 r 2 at (-12.015, 41.3) reference; C10 r 2 at (-12.015, 17.5); A1 r 4 centre (-12.015, 41.3) between (-8.015, 41.3) and (-16.015, 41.3) reference; 2 further points
  constraints: 10 end point, 7 point on line, 4 centre point, 3 perpendicular, 2 coincident, 2 midpoint, 1 vertical
  dimensions: "d210" = 4 diameter of C6; "d211" = 4 diameter of C7; "d212" = 4 diameter of C8; "d213" = 4 diameter of C10
extrude "돌출25" cut sketch "스케치23" distance "d214" = 34; taper "d216" = 0 deg; dims "d215" = 20, "d217" = 0
sketch "스케치24"
  geometry: C1 r 2 at (28, 17.5) reference; 2 further points
  constraints: 1 coincident
hole "구멍3" sketch "스케치24" at (28, 17.5) diameter "d218" = 4; stored, may be unused: countersink angle "d222" = 90 deg, drill point angle "d224" = 118 deg; dims "d219" = 6, "d220" = 6.2, "d221" = 3, "d223" = 8
sketch "스케치25"
  geometry: C1 r 2 at (68, 17.5) reference; 2 further points
  constraints: 1 coincident
hole "구멍4" sketch "스케치25" at (68, 17.5) diameter "d225" = 4; stored, may be unused: countersink angle "d229" = 90 deg, drill point angle "d231" = 118 deg; dims "d226" = 6, "d227" = 6.2, "d228" = 3, "d230" = 8
sketch "스케치26"
  geometry: C1 r 2 at (-25, -2) reference; C2 r 3.1 at (-25, -2); 1 further point
  constraints: 1 centre point, 1 coincident
  dimensions: "d232" = 6.2 diameter of C2
extrude "돌출26" cut sketch "스케치26" distance "d233" = 34; taper "d235" = 0 deg; dims "d234" = 3, "d236" = 0
sketch "스케치27"
  geometry: L1 (20, -12.5)-(0, -12.5) reference; L2 (20, -12.5)-(20, 11.5) reference; L3 (0, 11.5)-(20, 11.5) reference; L4 (0, 0)-(0, 11.5) reference; L5 (0, -12.5)-(0, 0) reference; C1 r 2 at (9.985, -2) reference; C2 r 3.1 at (9.985, -2); 1 further point
  constraints: 1 centre point, 1 coincident
  dimensions: "d237" = 6.2 diameter of C2
extrude "돌출27" cut sketch "스케치27" distance "d238" = 3; taper "d239" = 0 deg
sketch "스케치28"
  geometry: L1 (-53.47, 16)-(-58, 16) reference; L2 (0, 16)-(-53.47, 16) reference; L3 (0, 16)-(0, 0) reference; L4 (20, 0)-(0, 0) reference; L5 (20, 31)-(20, 0) reference; L6 (20, 31)-(-58, 31) reference; L7 (-58, 16)-(-58, 31) reference; C1 r 2 at (-8, 18.5) reference; C2 r 2 at (-48, 18.5) reference; C3 r 6 at (-48, 18.5); C4 r 6 at (-8, 18.5); 1 further point
  constraints: 2 centre point, 2 coincident
  dimensions: "d240" = 12 diameter of C3; "d241" = 12 diameter of C4
extrude "돌출28" cut sketch "스케치28" extent not by distance; stored distance "d242" = 0; taper "d243" = 0 deg
fillet "모깎기7" dims "d244" = 2
sketch "스케치29"
  geometry: L1 (-83.923, 43.982)-(145.526, 43.982); L2 (145.526, 43.982)-(145.526, -44.181); L3 (145.526, -44.181)-(-83.923, -44.181); L4 (-83.923, -44.181)-(-83.923, 43.982); 1 further point
  constraints: 8 end point, 2 parallel, 1 horizontal, 1 perpendicular
extrude "돌출29" cut sketch "스케치29" extent not by distance; stored distance "d245" = 0; taper "d246" = 0 deg
chamfer "모따기3" distance "d247" = 4; stored, may be unused: second distance "d248" = 2, angle "d249" = 45 deg
sketch "스케치30"
  geometry: C1 r 4.4 at (13, 18) reference; C2 r 5 at (13, 18); 1 further point
  constraints: 1 centre point, 1 coincident
  dimensions: "d250" = 10 diameter of C2
extrude "돌출30" cut sketch "스케치30" extent not by distance; stored distance "d251" = 0; taper "d252" = 0 deg
sketch "스케치31"
  geometry: C1 r 11.3 at (0, 0) reference; C2 r 2 at (0, 8) reference; C3 r 2 at (8, 0) reference; C4 r 2 at (0, -8) reference; C5 r 2 at (-8, 0) reference; C6 r 5.25 at (0, 0) reference; C7 r 11.8 at (0, 0); C8 r 5.55 at (0, 0); 1 further point
  constraints: 2 centre point, 2 coincident
  dimensions: "d253" = 0.3 radial gap between concentric circles of C8 C6; "d254" = 0.5 radial gap between concentric circles of C1 C7
  node "투영된 루프25"
extrude "돌출31" cut sketch "스케치31" extent not by distance; stored distance "d255" = 0; taper "d256" = 0 deg
extrude "돌출32" cut sketch "스케치31" extent not by distance; stored distance "d257" = 0; taper "d258" = 0 deg
node "솔리드1"
node "투영된 루프1"
node "투영된 루프2"
node "투영된 루프3"
node "투영된 루프4"
node "투영된 루프5"
node "투영된 루프6"
node "투영된 루프7"
node "투영된 루프8"
node "투영된 루프9"
node "투영된 루프10"
node "투영된 루프11"
node "투영된 루프12"
node "투영된 루프13"
node "투영된 루프14"
node "투영된 루프15"
node "투영된 루프16"
node "투영된 루프19"
node "투영된 루프20"
node "투영된 루프22"
node "투영된 루프23"
node "투영된 루프24"
feature "A9D066F2-1C7D-4E18-AEED-F7BC21143FA4" dims "d88" = 4, "d89" = 6, "d90" = 6.2, "d91" = 4, "d92" = 90 deg, "d93" = 8, "d94" = 0
